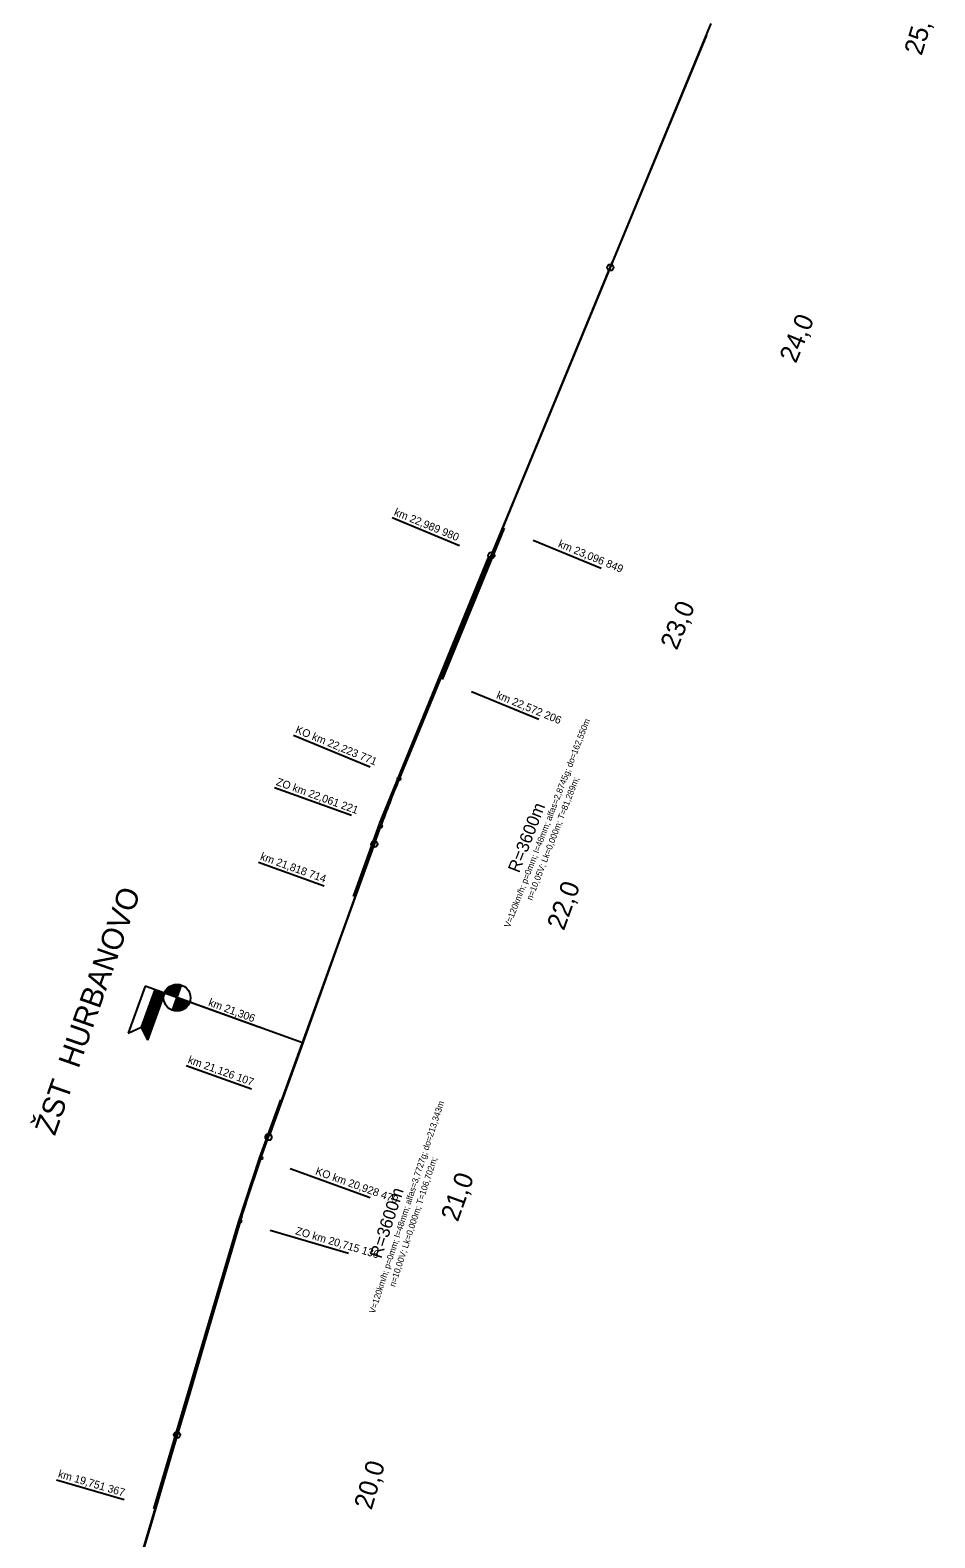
# Model space of a CAD drawing. Extents: x -504999 to -493096, y -1330712 to -1305226.
# Drawn here: x -495998 to -493096, y -1319679 to -1314840 of the extents above; entities that cross this region are included whole.
import ezdxf

# ---------------------------------------------------------------- set-up
doc = ezdxf.new("R2010")
doc.units = 0
for name, color, linetype in [('0_HM', 7, 'Continuous'), ('0_obluky', 7, 'Continuous'), ('0_popis oblukov', 7, 'Continuous'), ('0_STANICE', 7, 'Continuous'), ('0_stanicenie oblukov', 7, 'Continuous'), ('dotyčnice', 7, 'Continuous'), ('Level 1', 7, 'Continuous'), ('PHS', 7, 'Continuous')]:
    doc.layers.add(name, color=color, linetype=linetype)

msp = doc.modelspace()

# ---------------------------------------------------------------- linework, layer by layer
at = {"layer": '0_HM'}
for centre in [(-494136.7, -1315601.4), (-494518.3, -1316525.7), (-494894, -1317452.4), (-495233.6, -1318393), (-495526.9, -1319348.8)]:
    msp.add_circle(centre, 10, dxfattribs=at)
at = {"layer": '0_obluky'}
for p, q in [((-494814.6, -1317243.2), (-493813.4, -1314818.5)), ((-495257.8, -1318460.3), (-494873.2, -1317394.8)), ((-495965.7, -1320834.8), (-495324.3, -1318662.9))]:
    msp.add_line(p, q, dxfattribs=at)
for centre in [(-494814.6, -1317243.2), (-494873.2, -1317394.8), (-495257.8, -1318460.3), (-495324.3, -1318662.9)]:
    msp.add_circle(centre, 5, dxfattribs=at)
for centre, start, end in [((-491487.1, -1318617.2), 157.5635, 160.1505), ((-491871.7, -1319682.6), 160.1505, 163.546)]:
    msp.add_arc(centre, 3600, start, end, dxfattribs=at)
at = {"layer": '0_STANICE'}
for p, q in [((-495629.6, -1317908.5), (-495684, -1318059.6)), ((-495264.1, -1318040.2), (-495629.6, -1317908.5)), ((-495536.7, -1317941.9), (-495551.7, -1317910.2)), ((-495530.1, -1317944.3), (-495547.4, -1317907.6)), ((-495525.7, -1317941.9), (-495542.8, -1317905.5)), ((-495541.6, -1317985.9), (-495512.4, -1317905)), ((-495523.3, -1317935.2), (-495538.1, -1317903.9)), ((-495520.9, -1317928.6), (-495533, -1317902.9)), ((-495518.5, -1317921.9), (-495527.7, -1317902.4)), ((-495516.1, -1317915.3), (-495522, -1317902.7)), ((-495598.5, -1317919.7), (-495641.8, -1318039.8)), ((-495567.5, -1317930.9), (-495621.9, -1318082)), ((-495592.3, -1317999.9), (-495612.2, -1317957.7)), ((-495589.9, -1317993.3), (-495609.8, -1317951)), ((-495587.6, -1317986.6), (-495607.4, -1317944.4)), ((-495585.2, -1317980), (-495605, -1317937.7)), ((-495582.8, -1317973.3), (-495602.6, -1317931.1)), ((-495580.4, -1317966.7), (-495600.2, -1317924.4)), ((-495578, -1317960), (-495596.6, -1317920.4)), ((-495575.6, -1317953.4), (-495590, -1317922.8)), ((-495573.2, -1317946.7), (-495583.3, -1317925.2)), ((-495573.2, -1317946.7), (-495583.3, -1317925.2)), ((-495570.8, -1317940.1), (-495576.7, -1317927.6)), ((-495570.8, -1317940.1), (-495576.7, -1317927.6)), ((-495568.4, -1317933.4), (-495570, -1317930)), ((-495563.3, -1317932.4), (-495565.9, -1317927)), ((-495124.4, -1318090.5), (-495563.4, -1317932.3)), ((-495556.7, -1317934.8), (-495562.8, -1317921.7)), ((-495550, -1317937.1), (-495559.4, -1317917.2)), ((-495543.4, -1317939.5), (-495555.7, -1317913.4)), ((-495515.6, -1317986.9), (-495530.5, -1317955.2)), ((-495510.8, -1317985.3), (-495528.1, -1317948.5)), ((-495506.3, -1317983.2), (-495523.4, -1317946.7)), ((-495502, -1317980.5), (-495516.8, -1317949.1)), ((-495498, -1317977.3), (-495510.1, -1317951.5)), ((-495494.3, -1317973.4), (-495503.5, -1317953.9)), ((-495490.9, -1317968.9), (-495496.8, -1317956.3)), ((-495609.1, -1318046.5), (-495629, -1318004.2)), ((-495606.7, -1318039.8), (-495626.6, -1317997.6)), ((-495604.3, -1318033.2), (-495624.2, -1317990.9)), ((-495601.9, -1318026.5), (-495621.8, -1317984.3)), ((-495599.5, -1318019.9), (-495619.4, -1317977.6)), ((-495597.1, -1318013.2), (-495617, -1317971)), ((-495594.7, -1318006.6), (-495614.6, -1317964.3)), ((-495537.6, -1317987.2), (-495540.1, -1317981.8)), ((-495531.5, -1317988.2), (-495537.7, -1317975.2)), ((-495525.9, -1317988.5), (-495535.3, -1317968.5)), ((-495520.6, -1317988), (-495532.9, -1317961.9)), ((-495684, -1318059.6), (-495641.8, -1318039.8)), ((-495641.8, -1318039.8), (-495621.9, -1318082)), ((-495621.1, -1318079.8), (-495641, -1318037.5)), ((-495618.7, -1318073.1), (-495638.6, -1318030.9)), ((-495616.3, -1318066.5), (-495636.2, -1318024.2)), ((-495613.9, -1318059.8), (-495633.8, -1318017.6)), ((-495611.5, -1318053.2), (-495631.4, -1318010.9))]:
    msp.add_line(p, q, dxfattribs=at)
msp.add_circle((-495527, -1317945.5), 43, dxfattribs=at)
at = {"layer": '0_stanicenie oblukov'}
for p, q in [((-494907, -1317205), (-495153.3, -1317103.3)), ((-494967.3, -1317360.9), (-495214.6, -1317271.6)), ((-495163.8, -1318494.2), (-494907, -1318586.9)), ((-495228.4, -1318691.3), (-494976.4, -1318765.7))]:
    msp.add_line(p, q, dxfattribs=at)
at = {"layer": 'dotyčnice'}
for p, q in [((-494814.5, -1317242.9), (-493828.7, -1314855.6)), ((-494814.5, -1317242.9), (-494130, -1315583.5)), ((-495231.9, -1318388.3), (-494892.1, -1317447.1)), ((-495950, -1320781.4), (-495319.2, -1318645.8))]:
    msp.add_line(p, q, dxfattribs=at)
at = {"layer": 'Level 1'}
for p, q in [((-493828.7, -1314855.6), (-494130, -1315583.5)), ((-494130, -1315583.5), (-494439.9, -1316334.3))]:
    msp.add_line(p, q, dxfattribs=at)
for points in [[(-494439.9, -1316334.3), (-494507.8, -1316499.4), (-494600.5, -1316723.2), (-494748.1, -1317082.1), (-494814.5, -1317242.9)], [(-494892.1, -1317447.1), (-495011.8, -1317779.1), (-495128, -1318101.6), (-495231.9, -1318388.3)], [(-495319.2, -1318645.8), (-495399, -1318917.3), (-495440, -1319054.9), (-495488.6, -1319220.8), (-495529.8, -1319360.2), (-495541.6, -1319400.2), (-495607.3, -1319622.1), (-495638.3, -1319726.1), (-495723, -1320013.6), (-495808.7, -1320301.9), (-495896.2, -1320599.5), (-495950, -1320781.4)]]:
    msp.add_lwpolyline(points, dxfattribs=at)
at = {"layer": 'PHS'}
for p, q in [((-494620.4, -1316494.4), (-494836.7, -1316405.1)), ((-494674.8, -1316924), (-494476.5, -1316438.2)), ((-494384.1, -1316476.4), (-494166, -1316566.5)), ((-494877.1, -1317387.8), (-494528, -1316532.6)), ((-494582.3, -1316962.1), (-494365.7, -1317051.6)), ((-494961.2, -1317620.9), (-494877.2, -1317388.1)), ((-495055.3, -1317586.9), (-495265.5, -1317511)), ((-495288.6, -1318239.1), (-495497.5, -1318163.6)), ((-495697, -1319557.8), (-495913.5, -1319493.9))]:
    msp.add_line(p, q, dxfattribs=at)
msp.add_lwpolyline([(-495601.1, -1319586.1), (-495329.5, -1318666.6), (-495261.6, -1318458.9), (-495194.5, -1318273)], dxfattribs=at)

# ---------------------------------------------------------------- texts
at = {"layer": '0_HM'}
for s, rotation, p in [('25,0', 73.0848, (-493138.1, -1314923.7)), ('24,0', 67.5635, (-493541.2, -1315911.5)), ('23,0', 67.5635, (-493923.4, -1316832.4)), ('22,0', 70.1505, (-494285.8, -1317732.3)), ('21,0', 70.1505, (-494626.3, -1318667.4)), ('20,0', 73.546, (-494903.1, -1319592.2))]:
    msp.add_text(s, height=60, rotation=rotation, dxfattribs=at).set_placement(p)
at = {"layer": '0_popis oblukov'}
for s, height, rotation, p in [('V=120km/h; p=0mm; I=48mm; alfas=2,8745g; do=162,550m', 20, 68.857, (-494459.5, -1317722.2)), ('n=10,05V; Lk=0,000m; T=81,289m;', 20, 68.857, (-494388, -1317634.4)), ('R=3600m', 40, 68.857, (-494429.3, -1317547.1)), ('V=120km/h; p=0mm; I=48mm; alfas=3,7727g; do=213,343m', 20, 71.8483, (-494892.5, -1318960.8)), ('n=10,00V; Lk=0,000m; T=106,702m;', 20, 71.8483, (-494827.5, -1318875)), ('R=3600m', 40, 71.8483, (-494871.7, -1318784.8))]:
    msp.add_text(s, height=height, rotation=rotation, dxfattribs=at).set_placement(p)
at = {"layer": '0_STANICE'}
for s, height, rotation, p in [('ŽST  HURBANOVO', 70, 70.6378, (-495919.1, -1318391.1)), ('km 21,306', 25, 339.4991, (-495428.6, -1317970))]:
    msp.add_text(s, height=height, rotation=rotation, dxfattribs=at).set_placement(p)
at = {"layer": '0_stanicenie oblukov'}
for s, rotation, p in [('KO km 22,223 771', 337.5635, (-495149.5, -1317094.1)), ('ZO km 22,061 221', 340.1505, (-495211.2, -1317262.2)), ('KO km 20,928 479', 340.1505, (-495085.1, -1318512)), ('ZO km 20,715 136', 343.546, (-495148.8, -1318704.3))]:
    msp.add_text(s, height=25, rotation=rotation, dxfattribs=at).set_placement(p)
at = {"layer": 'PHS'}
for s, rotation, p in [('km 22,989 980', 337.5635, (-494832.9, -1316395.9)), ('km 23,096 849', 337.5635, (-494306.3, -1316497.7)), ('km 22,572 206', 337.5635, (-494504.6, -1316983.4)), ('km 21,818 714', 340.1505, (-495262.1, -1317501.6)), ('km 21,126 107', 340.1505, (-495494.1, -1318154.2)), ('km 19,751 367', 343.546, (-495910.6, -1319484.3))]:
    msp.add_text(s, height=25, rotation=rotation, dxfattribs=at).set_placement(p)

doc.saveas('drawing.dxf')
